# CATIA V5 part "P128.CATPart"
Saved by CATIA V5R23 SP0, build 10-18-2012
Part number: P128
Definition: Vis H M8x16
Bounding box of the stored display mesh (mm): x -16 to 5.45, y -6.5 to 6.5, z -7.506 to 7.506
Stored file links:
  C:\wamp\www\COURS\CONCEPTION GMP1\TITRE 02-SEMESTRE 2\03-TP7-PRESSE MECANIQUE\eleve\P128.CATPart
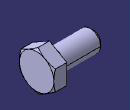
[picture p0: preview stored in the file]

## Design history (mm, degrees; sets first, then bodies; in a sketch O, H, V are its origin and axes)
Parameters
  Material = "St"
  Designation = "M8"
  d_dia = 8 mm
  l_length = 16 mm
  k_max_head_depth = 5.45 mm
  r_min = 0.4 mm
  s_nom_across_flats = 13 mm
  dw_min = 11.63 mm
  c_max = 0.6 mm
  P_pitch = 1.25 mm
Body1 "PartBody" (main body)
  Sketch1 on yz-plane, origin (0, 0, 0), H (0, 1, 0), V (0, 0, 1)
    circle A1 centre (0, 0) radius 5.815
    radius A1 = 5.815 {= dw_min /2}
  Pad1: profile Sketch1, direction (1, 0, 0), length 0.6 {= c_max}
  Sketch2 on face of Pad1, origin (0.6, 0, 0), H (0, 1, 0), V (0, 0, 1)
    point P1 (6.5, -3.7528)
    point P2 (6.5, 3.7528)
    point P3 (0, 7.5056)
    point P4 (-6.5, 3.7528)
    point P5 (-6.5, -3.7528)
    point P6 (0, -7.5056)
    point P7 (6.5, 0)
    line L1 (6.5, -3.7528) -> (6.5, 3.7528)
    line L2 (6.5, 3.7528) -> (0, 7.5056)
    line L3 (0, 7.5056) -> (-6.5, 3.7528)
    line L4 (-6.5, 3.7528) -> (-6.5, -3.7528)
    line L5 (-6.5, -3.7528) -> (0, -7.5056)
    line L6 (0, -7.5056) -> (6.5, -3.7528)
    construction line L7 (0, 0) -> (6.5, 0)
    construction circle A1 centre (0, 0) radius 7.5056
    construction arc A2 centre (-6.5, -3.7528) radius 7.5056 from (-6.5, 3.7528) to (0, -7.5056) cw
    construction arc A3 centre (6.5, 3.7528) radius 7.5056 from (0, 7.5056) to (6.5, -3.7528) ccw
    point P8 (-6.5, -3.7528)
    point P9 (6.5, 3.7528)
    distance L1 L4 = 13 {= s_nom_across_flats}
    horizontal: L7 H
    coincidence: A1 P1, A1 P2, A1 P3, A1 P4, A1 P5, A1 P6, A2 P4, A2 P6, A2 O, P8 P5, A3 P3, A3 P1, A3 O, P9 P2
    midpoint: P7 L1
  Pad2: profile Sketch2, direction (1, 0, 0), length 4.85 {= k_max_head_depth -c_max}
  Sketch3 on zx-plane, origin (0, 0, 0), H (-1, 0, 0), V (0, 0, 1)
    point P1 (-5.45, 6.4968)
    axis line L1 (-94.6904, 0) -> (76.7146, 0)
    reference intersected line E1 through (1000000, 0) direction (-1, 0) from xy-plane
    line L2 (-4.8676, 7.5056) -> (-5.45, 6.4968)
    line L3 (-4.8676, 7.5056) -> (-5.45, 7.5056)
    line L4 (-5.45, 7.5056) -> (-5.45, 6.4968)
    reference projected line E2 (-0.8, 7.5056) -> (-18.28, 7.5056) from edge [face of Pad2 | face of Pad2]
    distance P1 H = 6.4968 {= s_nom_across_flats /2.001}
    distance P1 V = 5.45 {= k_max_head_depth}
    angle L4 L2 = 30
    horizontal: L1 H, L3 H
    coincidence: L1 E1, L3 E2
    vertical: L4 V
  Groove1: profile Sketch3, axis Sketch3.L1, angle 360
  Sketch4 on face of Pad1, origin (0, 0, 0), H (0, -1, 0), V (0, 0, 1)
    circle A1 centre (0, 0) radius 3.9024
    radius A1 = 3.9024 {= d_dia /2.05}
  Pad3: profile Sketch4, direction (-1, 0, 0), length 16 {= l_length}
  Fillet1: radius 0.4 {= r_min}, on edge [face of Pad3 | face of Pad1]
  Chamfer1: length 1.25 {= P_pitch}, angle 45, on edge [face of Pad3 | face of Pad3]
